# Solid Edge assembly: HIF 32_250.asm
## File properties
Title: Zylinder
Author: ahadarics
Template: iso assembly.asm
Last saved by: ahadarics
Revision: 44
Application: Solid Edge
Username: ahadarics
Dokumentum tartalom típus: 1
Document Number: HIF 32/250
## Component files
Prfilrohr 32_250.par
Mutter.par
Kolbenstange 32_250.par
Kit_1.par
Kit_2.par
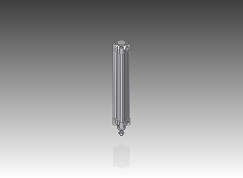
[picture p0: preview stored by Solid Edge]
